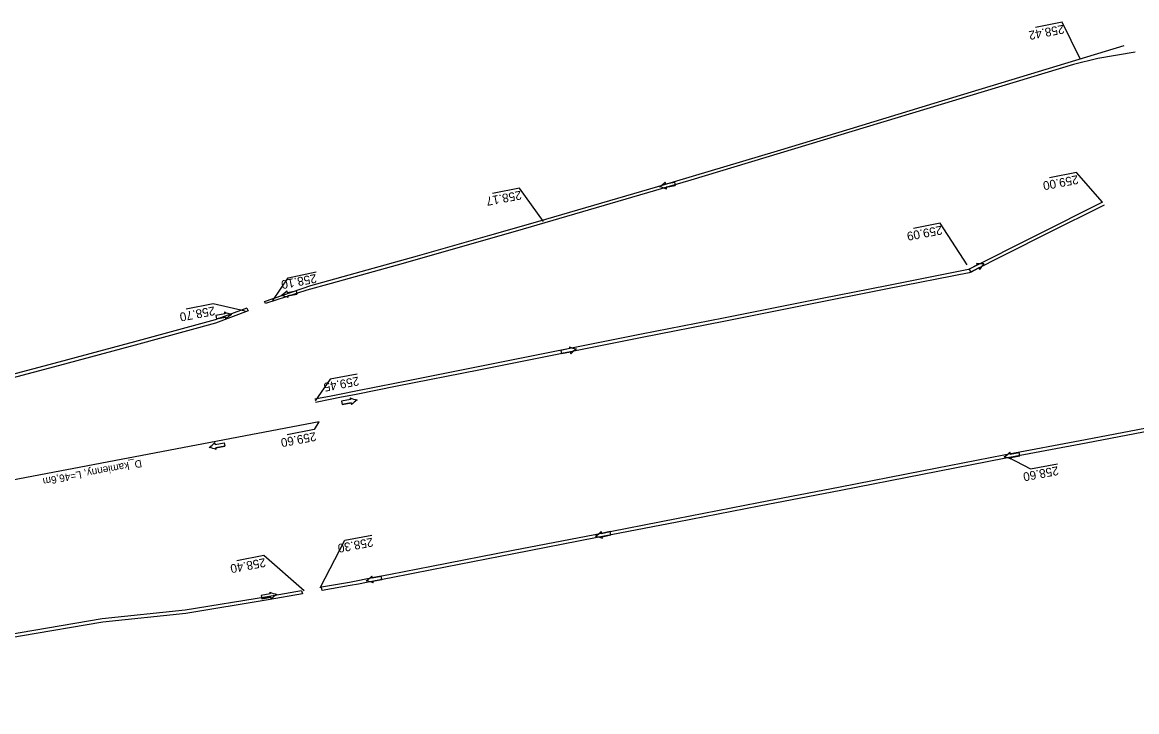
# Model space of a CAD drawing. Extents: x -1 to 65640748, y -22 to 5530284.
# Drawn here: x 6562491.8 to 6562625.6, y 5529613.4 to 5529696.1 of the extents above; entities that cross this region are included whole.
import ezdxf

# ---------------------------------------------------------------- set-up
doc = ezdxf.new("R2010")
doc.units = 0
for name, color, linetype in [('TOR_PS_ODW-drenaze', 7, 'Continuous'), ('TOR_PS_OPIS_O-opisy rurociagow', 7, 'Continuous'), ('TOR_PS_OPIS_T-INFO', 7, 'Continuous'), ('TOR_PS_T-rowy otwarte umocnione', 7, 'Continuous')]:
    doc.layers.add(name, color=color, linetype=linetype)

msp = doc.modelspace()

# ---------------------------------------------------------------- linework, layer by layer
at = {"layer": 'TOR_PS_ODW-drenaze'}
msp.add_lwpolyline([(6562527.49, 5529648.17), (6562489.84, 5529641.03), (6562486.61, 5529639.81), (6562481.92, 5529638.92)], dxfattribs=at)
at = {"layer": 'TOR_PS_OPIS_O-opisy rurociagow'}
for p, q in [((6562569.08, 5529676.73), (6562570.15, 5529676.95)), ((6562569.08, 5529676.73), (6562570.15, 5529676.95)), ((6562570.23, 5529676.55), (6562569.16, 5529676.34)), ((6562569.16, 5529676.34), (6562570.23, 5529676.55)), ((6562570.15, 5529676.95), (6562570.23, 5529676.55)), ((6562570.15, 5529676.95), (6562570.23, 5529676.55)), ((6562606.52, 5529667.01), (6562605.55, 5529666.52)), ((6562606.52, 5529667.01), (6562605.55, 5529666.52)), ((6562605.55, 5529666.52), (6562605.72, 5529666.16)), ((6562605.55, 5529666.52), (6562605.72, 5529666.16)), ((6562605.72, 5529666.16), (6562606.7, 5529666.65)), ((6562606.7, 5529666.65), (6562605.72, 5529666.16)), ((6562523.64, 5529663.7), (6562524.71, 5529663.92)), ((6562523.64, 5529663.7), (6562524.71, 5529663.92)), ((6562524.79, 5529663.52), (6562523.72, 5529663.31)), ((6562523.72, 5529663.31), (6562524.79, 5529663.52)), ((6562524.71, 5529663.92), (6562524.79, 5529663.52)), ((6562524.71, 5529663.92), (6562524.79, 5529663.52)), ((6562516.18, 5529661.14), (6562515.1, 5529660.95)), ((6562516.18, 5529661.14), (6562515.1, 5529660.95)), ((6562515.1, 5529660.95), (6562515.17, 5529660.56)), ((6562515.1, 5529660.95), (6562515.17, 5529660.56)), ((6562515.17, 5529660.56), (6562516.25, 5529660.75)), ((6562516.25, 5529660.75), (6562515.17, 5529660.56)), ((6562557.58, 5529656.96), (6562556.51, 5529656.75)), ((6562557.58, 5529656.96), (6562556.51, 5529656.75)), ((6562556.51, 5529656.75), (6562556.59, 5529656.36)), ((6562556.51, 5529656.75), (6562556.59, 5529656.36)), ((6562556.59, 5529656.36), (6562557.66, 5529656.57)), ((6562557.66, 5529656.57), (6562556.59, 5529656.36)), ((6562531.25, 5529650.86), (6562530.18, 5529650.66)), ((6562531.25, 5529650.86), (6562530.18, 5529650.66)), ((6562530.18, 5529650.66), (6562530.25, 5529650.27)), ((6562530.18, 5529650.66), (6562530.25, 5529650.27)), ((6562530.25, 5529650.27), (6562531.32, 5529650.46)), ((6562531.32, 5529650.46), (6562530.25, 5529650.27)), ((6562515.01, 5529645.45), (6562516.08, 5529645.67)), ((6562515.01, 5529645.45), (6562516.08, 5529645.67)), ((6562516.08, 5529645.67), (6562516.16, 5529645.27)), ((6562516.08, 5529645.67), (6562516.16, 5529645.27)), ((6562516.16, 5529645.27), (6562515.09, 5529645.06)), ((6562515.09, 5529645.06), (6562516.16, 5529645.27)), ((6562611.53, 5529644.51), (6562610.46, 5529644.3)), ((6562610.46, 5529644.3), (6562611.53, 5529644.51)), ((6562611.6, 5529644.11), (6562611.53, 5529644.51)), ((6562611.6, 5529644.11), (6562611.53, 5529644.51)), ((6562610.53, 5529643.91), (6562611.6, 5529644.11)), ((6562610.53, 5529643.91), (6562611.6, 5529644.11)), ((6562562.44, 5529634.99), (6562561.37, 5529634.78)), ((6562561.37, 5529634.78), (6562562.44, 5529634.99)), ((6562562.52, 5529634.59), (6562562.44, 5529634.99)), ((6562562.52, 5529634.59), (6562562.44, 5529634.99)), ((6562561.45, 5529634.38), (6562562.52, 5529634.59)), ((6562561.45, 5529634.38), (6562562.52, 5529634.59)), ((6562534.93, 5529629.64), (6562533.86, 5529629.44)), ((6562533.86, 5529629.44), (6562534.93, 5529629.64)), ((6562535.01, 5529629.25), (6562534.93, 5529629.64)), ((6562535.01, 5529629.25), (6562534.93, 5529629.64)), ((6562533.94, 5529629.04), (6562535.01, 5529629.25)), ((6562533.94, 5529629.04), (6562535.01, 5529629.25)), ((6562521.62, 5529627.51), (6562520.54, 5529627.32)), ((6562521.62, 5529627.51), (6562520.54, 5529627.32)), ((6562520.54, 5529627.32), (6562520.61, 5529626.93)), ((6562520.54, 5529627.32), (6562520.61, 5529626.93)), ((6562520.61, 5529626.93), (6562521.69, 5529627.12)), ((6562521.69, 5529627.12), (6562520.61, 5529626.93))]:
    msp.add_line(p, q, dxfattribs=at)
for points in [[(6562569.04, 5529676.95), (6562569.04, 5529676.95)], [(6562569.21, 5529676.12), (6562569.21, 5529676.12)], [(6562606.41, 5529667.21), (6562606.41, 5529667.21)], [(6562606.79, 5529666.45), (6562606.79, 5529666.45)], [(6562523.6, 5529663.92), (6562523.6, 5529663.92)], [(6562523.77, 5529663.09), (6562523.77, 5529663.09)], [(6562516.13, 5529661.36), (6562516.13, 5529661.36)], [(6562516.28, 5529660.52), (6562516.28, 5529660.52)], [(6562557.53, 5529657.18), (6562557.53, 5529657.18)], [(6562557.7, 5529656.35), (6562557.7, 5529656.35)], [(6562531.2, 5529651.08), (6562531.2, 5529651.08)], [(6562531.35, 5529650.24), (6562531.35, 5529650.24)], [(6562514.97, 5529645.67), (6562514.97, 5529645.67)], [(6562515.14, 5529644.84), (6562515.14, 5529644.84)], [(6562610.42, 5529644.53), (6562610.42, 5529644.53)], [(6562610.58, 5529643.69), (6562610.58, 5529643.69)], [(6562561.34, 5529635), (6562561.34, 5529635)], [(6562561.5, 5529634.17), (6562561.5, 5529634.17)], [(6562533.83, 5529629.66), (6562533.83, 5529629.66)], [(6562533.99, 5529628.82), (6562533.99, 5529628.82)], [(6562521.57, 5529627.73), (6562521.57, 5529627.73)], [(6562521.71, 5529626.9), (6562521.71, 5529626.9)]]:
    msp.add_lwpolyline(points, dxfattribs=at)
for centre, radius, start, end in [((6562565.56, 5529680.43), 4.92, 304.7037, 315.0855), ((6562565.56, 5529680.43), 4.92, 304.7037, 315.0855), ((6562567.34, 5529671.57), 4.92, 67.6658, 78.0476), ((6562567.34, 5529671.57), 4.92, 67.6658, 78.0476), ((6562568.62, 5529676.77), 0.458, 354.5097, 22.9709), ((6562568.62, 5529676.77), 0.458, 354.5097, 22.9709), ((6562568.75, 5529676.12), 0.458, 359.7803, 28.2416), ((6562568.75, 5529676.12), 0.458, 359.7803, 28.2416), ((6562607.02, 5529672.09), 4.92, 262.8862, 273.268), ((6562606.85, 5529667.32), 0.458, 195.0007, 223.462), ((6562607.02, 5529672.09), 4.92, 262.8862, 273.268), ((6562606.85, 5529667.32), 0.458, 195.0007, 223.462), ((6562611.06, 5529664.01), 4.92, 139.9241, 150.3059), ((6562611.06, 5529664.01), 4.92, 139.9241, 150.3059), ((6562607.15, 5529666.73), 0.458, 189.7301, 218.1913), ((6562607.15, 5529666.73), 0.458, 189.7301, 218.1913), ((6562520.12, 5529667.39), 4.92, 304.7037, 315.0855), ((6562520.12, 5529667.39), 4.92, 304.7037, 315.0855), ((6562521.9, 5529658.54), 4.92, 67.6658, 78.0476), ((6562521.9, 5529658.54), 4.92, 67.6658, 78.0476), ((6562523.18, 5529663.74), 0.458, 354.5097, 22.9709), ((6562523.18, 5529663.74), 0.458, 354.5097, 22.9709), ((6562523.31, 5529663.09), 0.458, 359.7803, 28.2416), ((6562523.31, 5529663.09), 0.458, 359.7803, 28.2416), ((6562518.1, 5529665.87), 4.92, 246.381, 256.7628), ((6562516.58, 5529661.35), 0.458, 178.4955, 206.9568), ((6562518.1, 5529665.87), 4.92, 246.381, 256.7628), ((6562516.58, 5529661.35), 0.458, 178.4955, 206.9568), ((6562516.7, 5529660.69), 0.458, 173.2249, 201.6861), ((6562516.7, 5529660.69), 0.458, 173.2249, 201.6861), ((6562519.68, 5529656.97), 4.92, 123.4189, 133.8007), ((6562519.68, 5529656.97), 4.92, 123.4189, 133.8007), ((6562559.41, 5529661.73), 4.92, 247.5239, 257.9057), ((6562557.99, 5529657.18), 0.458, 179.6384, 208.0997), ((6562559.41, 5529661.73), 4.92, 247.5239, 257.9057), ((6562557.99, 5529657.18), 0.458, 179.6384, 208.0997), ((6562558.12, 5529656.53), 0.458, 174.3678, 202.829), ((6562558.12, 5529656.53), 0.458, 174.3678, 202.829), ((6562561.17, 5529652.87), 4.92, 124.5617, 134.9436), ((6562561.17, 5529652.87), 4.92, 124.5617, 134.9436), ((6562533.17, 5529655.58), 4.92, 246.381, 256.7628), ((6562531.66, 5529651.06), 0.458, 178.4955, 206.9568), ((6562533.17, 5529655.58), 4.92, 246.381, 256.7628), ((6562531.66, 5529651.06), 0.458, 178.4955, 206.9568), ((6562531.78, 5529650.41), 0.458, 173.2249, 201.6861), ((6562531.78, 5529650.41), 0.458, 173.2249, 201.6861), ((6562534.76, 5529646.69), 4.92, 123.4189, 133.8007), ((6562534.76, 5529646.69), 4.92, 123.4189, 133.8007), ((6562511.49, 5529649.15), 4.92, 304.7037, 315.0855), ((6562511.49, 5529649.15), 4.92, 304.7037, 315.0855), ((6562514.55, 5529645.49), 0.458, 354.5097, 22.9709), ((6562514.55, 5529645.49), 0.458, 354.5097, 22.9709), ((6562513.27, 5529640.29), 4.92, 67.6658, 78.0476), ((6562513.27, 5529640.29), 4.92, 67.6658, 78.0476), ((6562514.68, 5529644.84), 0.458, 359.7803, 28.2416), ((6562514.68, 5529644.84), 0.458, 359.7803, 28.2416), ((6562606.98, 5529648.04), 4.92, 304.0624, 314.4442), ((6562606.98, 5529648.04), 4.92, 304.0624, 314.4442), ((6562610, 5529644.35), 0.458, 353.8684, 22.3297), ((6562610, 5529644.35), 0.458, 353.8684, 22.3297), ((6562608.66, 5529639.16), 4.92, 67.0245, 77.4064), ((6562608.66, 5529639.16), 4.92, 67.0245, 77.4064), ((6562610.12, 5529643.7), 0.458, 359.1391, 27.6003), ((6562610.12, 5529643.7), 0.458, 359.1391, 27.6003), ((6562557.88, 5529638.5), 4.92, 304.3165, 314.6983), ((6562557.88, 5529638.5), 4.92, 304.3165, 314.6983), ((6562560.92, 5529634.82), 0.458, 354.1225, 22.5837), ((6562560.92, 5529634.82), 0.458, 354.1225, 22.5837), ((6562559.6, 5529629.63), 4.92, 67.2786, 77.6604), ((6562559.6, 5529629.63), 4.92, 67.2786, 77.6604), ((6562561.04, 5529634.17), 0.458, 359.3931, 27.8544), ((6562561.04, 5529634.17), 0.458, 359.3931, 27.8544), ((6562530.37, 5529633.15), 4.92, 304.3165, 314.6983), ((6562530.37, 5529633.15), 4.92, 304.3165, 314.6983), ((6562533.41, 5529629.48), 0.458, 354.1225, 22.5837), ((6562533.41, 5529629.48), 0.458, 354.1225, 22.5837), ((6562532.09, 5529624.29), 4.92, 67.2786, 77.6604), ((6562532.09, 5529624.29), 4.92, 67.2786, 77.6604), ((6562533.53, 5529628.83), 0.458, 359.3931, 27.8544), ((6562533.53, 5529628.83), 0.458, 359.3931, 27.8544), ((6562523.54, 5529632.24), 4.92, 246.381, 256.7628), ((6562522.02, 5529627.72), 0.458, 178.4955, 206.9568), ((6562523.54, 5529632.24), 4.92, 246.381, 256.7628), ((6562522.02, 5529627.72), 0.458, 178.4955, 206.9568), ((6562522.14, 5529627.07), 0.458, 173.2249, 201.6861), ((6562522.14, 5529627.07), 0.458, 173.2249, 201.6861), ((6562525.12, 5529623.35), 4.92, 123.4189, 133.8007), ((6562525.12, 5529623.35), 4.92, 123.4189, 133.8007)]:
    msp.add_arc(centre, radius, start, end, dxfattribs=at)
at = {"layer": 'TOR_PS_OPIS_T-INFO'}
for points in [[(6562618.88, 5529691.77), (6562616.71, 5529696.14), (6562613.48, 5529695.52)], [(6562621.55, 5529674.53), (6562618.41, 5529678.1), (6562615.18, 5529677.47)], [(6562554.43, 5529672.21), (6562551.54, 5529676.23), (6562548.31, 5529675.6)], [(6562605.28, 5529667.04), (6562602.07, 5529672.03), (6562598.84, 5529671.4)], [(6562521.91, 5529662.75), (6562523.75, 5529665.45), (6562527.13, 5529666.2)], [(6562518.59, 5529661.47), (6562514.76, 5529662.34), (6562511.53, 5529661.71)], [(6562532.05, 5529653.9), (6562528.81, 5529653.28), (6562527.01, 5529650.69)], [(6562527.47, 5529648.18), (6562526.89, 5529647.25), (6562523.66, 5529646.63)], [(6562610.22, 5529643.94), (6562612.89, 5529642.55), (6562616.13, 5529643.15)], [(6562527.62, 5529628.25), (6562530.59, 5529633.97), (6562533.83, 5529634.57)], [(6562525.7, 5529627.89), (6562520.84, 5529632.12), (6562517.6, 5529631.5)]]:
    msp.add_lwpolyline(points, dxfattribs=at)
at = {"layer": 'TOR_PS_T-rowy otwarte umocnione'}
for points in [[(6562520.94, 5529662.63), (6562526.51, 5529664.53), (6562539.31, 5529668.1), (6562547.97, 5529670.57), (6562553.74, 5529672.23), (6562568.14, 5529676.44), (6562582.52, 5529680.73), (6562591.23, 5529683.36), (6562601.33, 5529686.43), (6562624.16, 5529693.36)], [(6562625.46, 5529692.56), (6562620.99, 5529691.79), (6562618.07, 5529691.09), (6562572.13, 5529677.2), (6562551.99, 5529671.31), (6562537.58, 5529667.2), (6562528.92, 5529664.78), (6562526.03, 5529663.98), (6562521.06, 5529662.37), (6562520.94, 5529662.63)], [(6562621.55, 5529674.53), (6562605.45, 5529666.47), (6562595.64, 5529664.52), (6562585.83, 5529662.57), (6562576.02, 5529660.63), (6562566.21, 5529658.68), (6562556.4, 5529656.73), (6562546.59, 5529654.78), (6562536.78, 5529652.83), (6562531.88, 5529651.86), (6562529.92, 5529651.47), (6562528.94, 5529651.27), (6562526.98, 5529650.88)], [(6562621.73, 5529674.19), (6562614.82, 5529670.73), (6562605.52, 5529666.08), (6562595.71, 5529664.13), (6562585.9, 5529662.18), (6562576.09, 5529660.23), (6562566.29, 5529658.28), (6562556.48, 5529656.34), (6562546.67, 5529654.39), (6562536.86, 5529652.44), (6562531.95, 5529651.47), (6562529.99, 5529651.08), (6562529.01, 5529650.88), (6562527.05, 5529650.49)], [(6562518.8, 5529661.84), (6562514.99, 5529660.42), (6562505.32, 5529657.76)], [(6562518.8, 5529661.84), (6562518.97, 5529661.49), (6562515.06, 5529660.02), (6562505.39, 5529657.37)], [(6562505.31, 5529657.78), (6562495.63, 5529655.17), (6562485.93, 5529652.62), (6562476.23, 5529650.11), (6562466.52, 5529647.65), (6562456.8, 5529645.24), (6562446.99, 5529643.27), (6562437.2, 5529641.26)], [(6562505.39, 5529657.39), (6562495.7, 5529654.78), (6562486.01, 5529652.22), (6562476.31, 5529649.72), (6562466.59, 5529647.26), (6562456.87, 5529644.85), (6562447.07, 5529642.88), (6562437.27, 5529640.87)], [(6562629.33, 5529647.88), (6562619.5, 5529646.02), (6562609.68, 5529644.16), (6562599.86, 5529642.25), (6562590.04, 5529640.34), (6562580.23, 5529638.44), (6562570.41, 5529636.53), (6562560.59, 5529634.62), (6562550.78, 5529632.72), (6562540.96, 5529630.81), (6562536.05, 5529629.86), (6562533.11, 5529629.29)], [(6562629.4, 5529647.49), (6562619.57, 5529645.63), (6562609.75, 5529643.76), (6562599.93, 5529641.86), (6562590.12, 5529639.95), (6562580.3, 5529638.04), (6562570.48, 5529636.14), (6562560.67, 5529634.23), (6562550.85, 5529632.32), (6562541.03, 5529630.42), (6562536.12, 5529629.46), (6562533.18, 5529628.89)], [(6562533.11, 5529629.29), (6562532.12, 5529629.09), (6562531.14, 5529628.9), (6562527.79, 5529628.32)], [(6562533.18, 5529628.89), (6562532.2, 5529628.7), (6562531.22, 5529628.51), (6562527.87, 5529627.92), (6562527.79, 5529628.32)], [(6562525.39, 5529627.9), (6562521.29, 5529627.18), (6562511.42, 5529625.58)], [(6562525.39, 5529627.9), (6562525.49, 5529627.51), (6562521.37, 5529626.79), (6562511.49, 5529625.18)], [(6562511.42, 5529625.58), (6562501.44, 5529624.52), (6562491.58, 5529622.85), (6562481.73, 5529621.09), (6562471.89, 5529619.3), (6562462.06, 5529617.51), (6562452.22, 5529615.72), (6562442.41, 5529613.76)], [(6562511.49, 5529625.18), (6562501.51, 5529624.13), (6562491.65, 5529622.46), (6562481.81, 5529620.69), (6562471.97, 5529618.9), (6562462.13, 5529617.11), (6562452.29, 5529615.32), (6562442.48, 5529613.37)]]:
    msp.add_lwpolyline(points, dxfattribs=at)

# ---------------------------------------------------------------- texts
at = {"layer": 'TOR_PS_OPIS_O-opisy rurociagow'}
msp.add_text('D_kamienny, L=46,6m', height=0.9, rotation=190.5985, dxfattribs=at).set_placement((6562506.11, 5529643.64))
at = {"layer": 'TOR_PS_OPIS_T-INFO'}
for s, rotation, p in [('258.42', 190.7159, (6562616.84, 5529695.85)), ('259.00', 190.7159, (6562618.54, 5529677.8)), ('258.17', 190.7159, (6562551.68, 5529675.93)), ('259.09', 190.7159, (6562602.2, 5529671.73)), ('258.10', 190.7506, (6562527.08, 5529665.93)), ('258.70', 190.7159, (6562514.89, 5529662.04)), ('259.45', 190.7159, (6562532.18, 5529653.61)), ('259.60', 190.7159, (6562527.03, 5529646.95)), ('258.60', 190.7506, (6562616.16, 5529642.85)), ('258.30', 190.7506, (6562533.87, 5529634.27)), ('258.40', 190.7159, (6562520.97, 5529631.82))]:
    msp.add_text(s, height=1.05, rotation=rotation, dxfattribs=at).set_placement(p)

doc.saveas('drawing.dxf')
